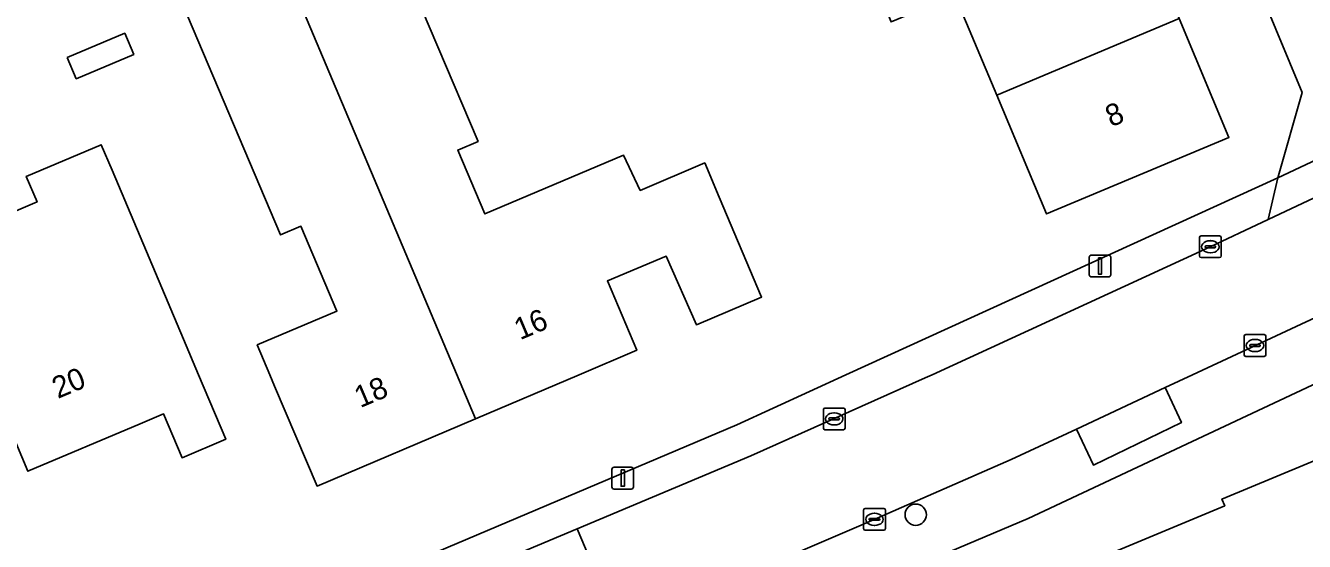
# Model space of a CAD drawing. Extents: x 158472 to 159562, y 388525 to 389606.
# Drawn here: x 158644.1 to 158703, y 388992.3 to 389016.1 of the extents above; entities that cross this region are included whole.
import ezdxf

# ---------------------------------------------------------------- set-up
doc = ezdxf.new("R2010")
doc.units = 0
for name, color, linetype in [('IMGEO_Boom', 7, 'Continuous'), ('IMGEO_Erf', 7, 'Continuous'), ('IMGEO_Kolk', 7, 'Continuous'), ('IMGEO_Lichtmast', 7, 'Continuous'), ('IMGEO_Pand', 7, 'Continuous'), ('IMGEO_Pand_nummerreeks', 7, 'Continuous'), ('IMGEO_Parkeervlak_open', 7, 'Continuous'), ('IMGEO_Rijbaan_lokaal_open', 7, 'Continuous'), ('IMGEO_Voetpad_open', 7, 'Continuous')]:
    doc.layers.add(name, color=color, linetype=linetype)

msp = doc.modelspace()

# ---------------------------------------------------------------- linework, layer by layer
at = {"layer": 'IMGEO_Boom'}
msp.add_circle((158685.082, 388993.555), 0.489, dxfattribs=at)
at = {"layer": 'IMGEO_Erf'}
for points in [[(158675.424, 389036.578), (158677.014, 389037.245), (158681.624, 389039.178), (158682.824, 389036.319), (158687.982, 389038.482), (158690.294, 389032.972), (158692.605, 389027.462), (158687.417, 389025.286), (158688.586, 389022.499), (158689.756, 389019.71), (158694.912, 389021.872), (158697.207, 389016.401), (158699.503, 389010.928), (158691.103, 389007.405), (158688.809, 389012.873), (158686.881, 389017.47), (158683.948, 389016.24), (158682.383, 389019.972), (158682.014, 389020.851), (158680.844, 389023.642), (158683.776, 389024.872), (158681.863, 389029.433), (158679.929, 389034.043), (158677.002, 389032.816)], [(158650.118, 389019.904), (158654.729, 389021.862), (158659.368, 389023.832), (158664.927, 389010.742), (158663.991, 389010.345), (158665.24, 389007.404), (158671.62, 389010.113), (158672.395, 389008.488), (158675.364, 389009.748), (158676.032, 389008.176), (158677.986, 389003.573), (158674.987, 389002.3), (158673.584, 389005.462), (158670.885, 389004.316), (158672.238, 389001.128), (158669.582, 389000), (158664.808, 388997.973), (158657.516, 388994.876), (158655.562, 388999.479), (158655.341, 389000), (158654.759, 389001.369), (158658.429, 389002.928), (158656.77, 389006.835), (158655.836, 389006.438)], [(158639.045, 389015.119), (158641.284, 389016.066), (158642.112, 389014.108), (158639.873, 389013.161), (158642.464, 389007.037), (158644.627, 389007.952), (158644.128, 389009.129), (158647.578, 389010.589), (158648.076, 389009.411), (158651.367, 389001.634), (158652.058, 389000), (158653.315, 388997.029), (158651.301, 388996.177), (158650.444, 388998.201), (158649.364, 388997.744), (158644.2, 388995.559), (158642.321, 389000), (158639.817, 389005.917), (158639.397, 389006.91), (158636.543, 389005.703), (158633.544, 389012.791)], [(158646.017, 389014.597), (158648.661, 389015.719), (158649.073, 389014.747), (158646.429, 389013.624)]]:
    msp.add_lwpolyline(points, close=True, dxfattribs=at)
for points in [[(158615.196, 388971.572), (158676.848, 388997.698), (158681.87, 389000), (158701.755, 389009.057), (158702.875, 389012.992), (158695.038, 389031.866)], [(158704.348, 389000), (158690.257, 388993.388), (158645.827, 388974.583), (158644.373, 388970.786), (158647.114, 388964.264), (158650.233, 388956.842), (158652.977, 388950.312), (158661.333, 388942.738)], [(158670.641, 388938.679), (158697.972, 388974.859), (158693.313, 388986.054), (158691.392, 388990.67), (158699.313, 388993.966), (158699.183, 388994.278), (158707.994, 388997.945)]]:
    msp.add_lwpolyline(points, dxfattribs=at)
at = {"layer": 'IMGEO_Kolk'}
for p, q in [((158698.146, 389005.466), (158698.146, 389006.318)), ((158698.221, 389006.392), (158699.073, 389006.392)), ((158698.634, 389006.172), (158698.659, 389006.172)), ((158699.147, 389006.318), (158699.147, 389005.466)), ((158699.073, 389005.392), (158698.221, 389005.392)), ((158698.405, 389005.886), (158698.405, 389005.898)), ((158698.843, 389005.849), (158698.445, 389005.849)), ((158698.448, 389005.935), (158698.846, 389005.935)), ((158698.657, 389005.612), (158698.632, 389005.612)), ((158698.889, 389005.898), (158698.889, 389005.886)), ((158700.277, 389001.845), (158701.129, 389001.845)), ((158700.202, 389000.919), (158700.202, 389001.771)), ((158700.461, 389001.339), (158700.461, 389001.351)), ((158700.899, 389001.302), (158700.501, 389001.302)), ((158700.504, 389001.388), (158700.902, 389001.388)), ((158700.69, 389001.625), (158700.715, 389001.625)), ((158700.945, 389001.351), (158700.945, 389001.339)), ((158701.203, 389001.771), (158701.203, 389000.919)), ((158701.129, 389000.845), (158700.277, 389000.845)), ((158700.713, 389001.065), (158700.688, 389001.065)), ((158680.829, 388997.54), (158680.829, 388998.392)), ((158680.904, 388998.466), (158681.756, 388998.466)), ((158681.83, 388998.392), (158681.83, 388997.54)), ((158681.088, 388997.96), (158681.088, 388997.972)), ((158681.526, 388997.923), (158681.128, 388997.923)), ((158681.131, 388998.009), (158681.529, 388998.009)), ((158681.317, 388998.246), (158681.342, 388998.246)), ((158681.572, 388997.972), (158681.572, 388997.96)), ((158681.756, 388997.466), (158680.904, 388997.466)), ((158681.34, 388997.686), (158681.315, 388997.686)), ((158682.682, 388992.916), (158682.682, 388993.768)), ((158682.757, 388993.842), (158683.609, 388993.842)), ((158683.17, 388993.622), (158683.195, 388993.622)), ((158683.683, 388993.768), (158683.683, 388992.916)), ((158682.941, 388993.336), (158682.941, 388993.348)), ((158683.379, 388993.299), (158682.981, 388993.299)), ((158682.984, 388993.385), (158683.382, 388993.385)), ((158683.193, 388993.062), (158683.168, 388993.062)), ((158683.425, 388993.348), (158683.425, 388993.336)), ((158683.609, 388992.842), (158682.757, 388992.842))]:
    msp.add_line(p, q, dxfattribs=at)
for points in [[(158698.146, 389005.466), (158698.146, 389006.318)], [(158698.221, 389006.392), (158699.073, 389006.392)], [(158699.147, 389006.318), (158699.147, 389005.466)], [(158699.073, 389005.392), (158698.221, 389005.392)], [(158700.277, 389001.845), (158701.129, 389001.845)], [(158700.202, 389000.919), (158700.202, 389001.771)], [(158701.203, 389001.771), (158701.203, 389000.919)], [(158701.129, 389000.845), (158700.277, 389000.845)], [(158680.829, 388997.54), (158680.829, 388998.392)], [(158680.904, 388998.466), (158681.756, 388998.466)], [(158681.83, 388998.392), (158681.83, 388997.54)], [(158681.756, 388997.466), (158680.904, 388997.466)], [(158682.682, 388992.916), (158682.682, 388993.768)], [(158682.757, 388993.842), (158683.609, 388993.842)], [(158683.683, 388993.768), (158683.683, 388992.916)], [(158683.609, 388992.842), (158682.757, 388992.842)]]:
    msp.add_lwpolyline(points, dxfattribs=at)
for centre, radius, start, end in [((158698.223, 389006.316), 0.0765, 91.55205, 178.44795), ((158698.223, 389006.316), 0.0765, 91.55205, 178.44795), ((158699.071, 389006.316), 0.0765, 1.55205, 88.44795), ((158699.071, 389006.316), 0.0765, 1.55205, 88.44795), ((158698.223, 389005.468), 0.0765, 181.55205, 268.44795), ((158698.223, 389005.468), 0.0765, 181.55205, 268.44795), ((158698.445, 389005.895), 0.0403, 85.87752, 175.75265), ((158698.442, 389005.885), 0.0366, 178.93798, 274.71019), ((158698.846, 389005.892), 0.043, 264.86636, 352.45326), ((158698.85, 389005.897), 0.0386, 1.73085, 96.63898), ((158699.071, 389005.468), 0.0765, 271.55205, 358.44795), ((158699.071, 389005.468), 0.0765, 271.55205, 358.44795), ((158700.279, 389001.769), 0.0765, 91.55205, 178.44795), ((158700.279, 389001.769), 0.0765, 91.55205, 178.44795), ((158701.127, 389001.769), 0.0765, 1.55205, 88.44795), ((158701.127, 389001.769), 0.0765, 1.55205, 88.44795), ((158700.501, 389001.348), 0.0403, 85.87752, 175.75265), ((158700.498, 389001.338), 0.0366, 178.93798, 274.71019), ((158700.902, 389001.345), 0.043, 264.86636, 352.45326), ((158700.906, 389001.35), 0.0386, 1.73085, 96.63898), ((158700.279, 389000.921), 0.0765, 181.55205, 268.44795), ((158700.279, 389000.921), 0.0765, 181.55205, 268.44795), ((158701.127, 389000.921), 0.0765, 271.55205, 358.44795), ((158701.127, 389000.921), 0.0765, 271.55205, 358.44795), ((158680.906, 388998.39), 0.0765, 91.55205, 178.44795), ((158680.906, 388998.39), 0.0765, 91.55205, 178.44795), ((158681.754, 388998.39), 0.0765, 1.55205, 88.44795), ((158681.754, 388998.39), 0.0765, 1.55205, 88.44795), ((158681.128, 388997.969), 0.0403, 85.87752, 175.75265), ((158681.125, 388997.959), 0.0366, 178.93798, 274.71019), ((158681.529, 388997.966), 0.043, 264.86636, 352.45326), ((158681.533, 388997.971), 0.0386, 1.73085, 96.63898), ((158680.906, 388997.542), 0.0765, 181.55205, 268.44795), ((158680.906, 388997.542), 0.0765, 181.55205, 268.44795), ((158681.754, 388997.542), 0.0765, 271.55205, 358.44795), ((158681.754, 388997.542), 0.0765, 271.55205, 358.44795), ((158682.759, 388993.766), 0.0765, 91.55205, 178.44795), ((158682.759, 388993.766), 0.0765, 91.55205, 178.44795), ((158683.607, 388993.766), 0.0765, 1.55205, 88.44795), ((158683.607, 388993.766), 0.0765, 1.55205, 88.44795), ((158682.981, 388993.345), 0.0403, 85.87752, 175.75265), ((158682.978, 388993.335), 0.0366, 178.93798, 274.71019), ((158683.382, 388993.342), 0.043, 264.86636, 352.45326), ((158683.386, 388993.347), 0.0386, 1.73085, 96.63898), ((158682.759, 388992.918), 0.0765, 181.55205, 268.44795), ((158682.759, 388992.918), 0.0765, 181.55205, 268.44795), ((158683.607, 388992.918), 0.0765, 271.55205, 358.44795), ((158683.607, 388992.918), 0.0765, 271.55205, 358.44795)]:
    msp.add_arc(centre, radius, start, end, dxfattribs=at)
for centre, major_axis, ratio, start_param, end_param in [((158698.633, 389005.892), (-0.387, 0.002), 0.722429, 4.712389, 7.853982), ((158698.658, 389005.892), (-0.39, 0.002), 0.717154, 1.570796, 4.712389), ((158700.689, 389001.345), (-0.387, 0.002), 0.722429, 4.712389, 7.853982), ((158700.714, 389001.345), (-0.39, 0.002), 0.717154, 1.570796, 4.712389), ((158681.316, 388997.966), (-0.387, 0.002), 0.722429, 4.712389, 7.853982), ((158681.341, 388997.966), (-0.39, 0.002), 0.717154, 1.570796, 4.712389), ((158683.169, 388993.342), (-0.387, 0.002), 0.722429, 4.712389, 7.853982), ((158683.194, 388993.342), (-0.39, 0.002), 0.717154, 1.570796, 4.712389)]:
    msp.add_ellipse(centre, major_axis=major_axis, ratio=ratio, start_param=start_param, end_param=end_param, dxfattribs=at)
at = {"layer": 'IMGEO_Lichtmast'}
for p, q in [((158693.072, 389004.606), (158693.072, 389005.406)), ((158693.072, 389005.406), (158693.072, 389004.606)), ((158693.172, 389005.506), (158693.962, 389005.506)), ((158693.962, 389005.506), (158693.172, 389005.506)), ((158694.062, 389005.406), (158694.062, 389004.606)), ((158694.062, 389004.606), (158694.062, 389005.406)), ((158693.962, 389004.506), (158693.172, 389004.506)), ((158693.172, 389004.506), (158693.962, 389004.506)), ((158671.096, 388994.839), (158671.096, 388995.639)), ((158671.096, 388995.639), (158671.096, 388994.839)), ((158671.196, 388995.739), (158671.986, 388995.739)), ((158671.986, 388995.739), (158671.196, 388995.739)), ((158672.086, 388995.639), (158672.086, 388994.839)), ((158672.086, 388994.839), (158672.086, 388995.639)), ((158671.986, 388994.739), (158671.196, 388994.739)), ((158671.196, 388994.739), (158671.986, 388994.739))]:
    msp.add_line(p, q, dxfattribs=at)
for points in [[(158693.492, 389005.381), (158693.642, 389005.381), (158693.642, 389004.631), (158693.492, 389004.631), (158693.492, 389005.381)], [(158671.516, 388995.614), (158671.666, 388995.614), (158671.666, 388994.864), (158671.516, 388994.864), (158671.516, 388995.614)]]:
    msp.add_lwpolyline(points, dxfattribs=at)
for centre, start, end in [((158693.172, 389005.406), 90, 180), ((158693.172, 389005.406), 90, 180), ((158693.962, 389005.406), 0, 90), ((158693.962, 389005.406), 360, 90), ((158693.172, 389004.606), 180, 270), ((158693.172, 389004.606), 180, 270), ((158693.962, 389004.606), 270, 0), ((158693.962, 389004.606), 270, 0), ((158671.196, 388995.639), 90, 180), ((158671.196, 388995.639), 90, 180), ((158671.986, 388995.639), 0, 90), ((158671.986, 388995.639), 360, 90), ((158671.196, 388994.839), 180, 270), ((158671.196, 388994.839), 180, 270), ((158671.986, 388994.839), 270, 0), ((158671.986, 388994.839), 270, 0)]:
    msp.add_arc(centre, 0.1, start, end, dxfattribs=at)
at = {"layer": 'IMGEO_Pand'}
for points in [[(158664.808, 388997.973), (158669.582, 389000), (158672.238, 389001.128), (158670.885, 389004.316), (158673.584, 389005.462), (158674.987, 389002.3), (158677.986, 389003.573), (158676.032, 389008.176), (158675.364, 389009.748), (158672.395, 389008.488), (158671.62, 389010.113), (158665.24, 389007.404), (158663.991, 389010.345), (158664.927, 389010.742), (158659.368, 389023.832), (158654.729, 389021.862)], [(158682.383, 389019.972), (158683.948, 389016.24), (158686.881, 389017.47), (158688.809, 389012.873), (158697.207, 389016.401), (158694.912, 389021.872), (158689.756, 389019.71), (158688.586, 389022.499)], [(158664.808, 388997.973), (158654.729, 389021.862), (158650.118, 389019.904), (158655.836, 389006.438), (158656.77, 389006.835), (158658.429, 389002.928), (158654.759, 389001.369), (158655.341, 389000), (158655.562, 388999.479), (158657.516, 388994.876)], [(158697.207, 389016.401), (158688.809, 389012.873), (158691.103, 389007.405), (158699.503, 389010.928)], [(158646.017, 389014.597), (158646.429, 389013.624), (158649.073, 389014.747), (158648.661, 389015.719)], [(158639.817, 389005.917), (158642.321, 389000), (158644.2, 388995.559), (158649.364, 388997.744), (158650.444, 388998.201), (158651.301, 388996.177), (158653.315, 388997.029), (158652.058, 389000), (158651.367, 389001.634), (158648.076, 389009.411), (158647.578, 389010.589), (158644.128, 389009.129), (158644.627, 389007.952), (158642.464, 389007.037)], [(158693.313, 388986.054), (158697.972, 388974.859), (158701.259, 388979.105), (158697.306, 388988.133), (158703.989, 388991.059), (158708.118, 388988.02), (158713.764, 388995.692), (158711.928, 389000), (158711.887, 389000.094), (158711.662, 389000), (158707.807, 388998.396), (158707.994, 388997.945), (158699.183, 388994.278), (158699.313, 388993.966), (158691.392, 388990.67)]]:
    msp.add_lwpolyline(points, close=True, dxfattribs=at)
at = {"layer": 'IMGEO_Parkeervlak_open'}
msp.add_lwpolyline([(158692.481, 388997.501), (158693.26, 388995.84), (158697.316, 388997.795), (158696.565, 388999.409)], close=True, dxfattribs=at)
at = {"layer": 'IMGEO_Rijbaan_lokaal_open'}
for points in [[(158601.851, 389031.612), (158602.187, 389030.899), (158641.722, 389047.425), (158668.118, 389058.458), (158688.082, 389043.319), (158689.958, 389044.098), (158691.297, 389040.872), (158693.979, 389034.415), (158697.841, 389036.019), (158698.899, 389033.47), (158695.038, 389031.866), (158702.875, 389012.992), (158701.755, 389009.057), (158712.826, 389014.266), (158709.235, 389015.859), (158706.255, 389023.142), (158703.674, 389029.291), (158697.03, 389045.201), (158668.409, 389067.056)], [(158698.385, 389005.769), (158701.31, 389007.145), (158701.755, 389009.057), (158681.87, 389000), (158676.848, 388997.698), (158615.196, 388971.572)], [(158613.777, 388969.44), (158623.761, 388973.64), (158626.342, 388974.726), (158666.906, 388991.81), (158669.486, 388992.898), (158677.486, 388996.27), (158685.513, 388999.85), (158685.84, 389000), (158698.385, 389005.769)]]:
    msp.add_lwpolyline(points, dxfattribs=at)
for points in [[(158716.887, 389008.886), (158720.963, 389010.783), (158722.372, 389011.439), (158726.454, 389013.362), (158727.832, 389014.007), (158731.934, 389015.926), (158732.275, 389016.087), (158730.105, 389020.689), (158714.806, 389013.493), (158701.31, 389007.145), (158698.385, 389005.769), (158685.84, 389000), (158685.513, 388999.85), (158677.486, 388996.27), (158669.486, 388992.898), (158671.441, 388988.302), (158675.334, 388989.969), (158682.574, 388993.068), (158689.479, 388996.098), (158692.481, 388997.501), (158696.565, 388999.409), (158697.829, 389000)], [(158714.806, 389013.493), (158712.826, 389014.266), (158701.755, 389009.057), (158701.31, 389007.145)], [(158671.441, 388988.302), (158669.486, 388992.898), (158666.906, 388991.81), (158668.877, 388987.204)]]:
    msp.add_lwpolyline(points, close=True, dxfattribs=at)
at = {"layer": 'IMGEO_Voetpad_open'}
for points in [[(158603.002, 388969.004), (158600.876, 388971.386), (158599.538, 388970.215), (158598.936, 388969.698), (158601.535, 388966.825), (158608.557, 388958.887), (158623.539, 388965.148), (158628.277, 388967.141), (158633.535, 388969.353), (158636.325, 388970.661), (158645.827, 388974.583), (158690.257, 388993.388), (158704.348, 389000), (158711.965, 389003.575), (158727.129, 389010.69), (158738.552, 389016.051)], [(158716.887, 389008.886), (158697.829, 389000), (158696.565, 388999.409), (158697.316, 388997.795), (158693.26, 388995.84), (158692.481, 388997.501), (158689.479, 388996.098), (158682.574, 388993.068), (158675.334, 388989.969), (158676.06, 388988.323), (158672.165, 388986.645), (158671.441, 388988.302), (158668.877, 388987.204), (158660.069, 388983.434), (158660.79, 388981.791), (158656.619, 388980.005), (158655.909, 388981.653), (158654.536, 388981.065), (158655.253, 388979.425), (158651.107, 388977.626), (158650.371, 388979.282), (158647.156, 388977.906), (158632.221, 388971.716)]]:
    msp.add_lwpolyline(points, dxfattribs=at)

# ---------------------------------------------------------------- texts
at = {"layer": 'IMGEO_Pand_nummerreeks'}
for s, rotation, p in [('8', 22.75341, (158694.078, 389011.386)), ('16', 23.0098, (158666.862, 389001.583)), ('20', 22.9355, (158645.582, 388998.882)), ('18', 23.0092, (158659.504, 388998.458))]:
    msp.add_text(s, height=1, rotation=rotation, dxfattribs=at).set_placement(p)

doc.saveas('drawing.dxf')
